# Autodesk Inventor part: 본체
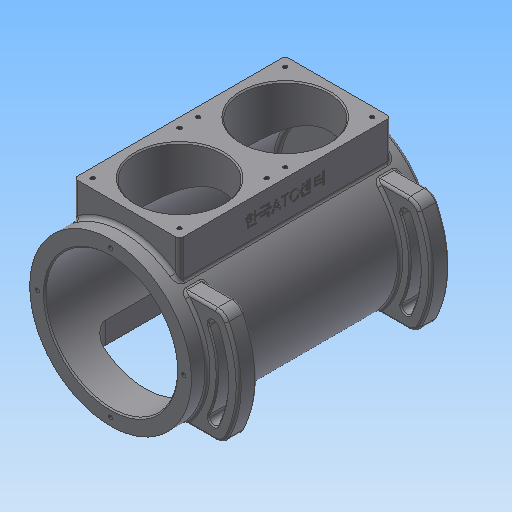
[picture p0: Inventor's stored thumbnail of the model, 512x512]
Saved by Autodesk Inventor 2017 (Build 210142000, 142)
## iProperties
Created: 2016-11
Part Number: 본체
Material: 알루미늄 6061
Document SubType Name: Modeling
Designer: mduedu
Density: 2.71 g/cm^3
Appearance: 기본값
Author: mduedu
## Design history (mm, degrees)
sketch "스케치1"
  geometry: C1 r 65 at (0, 0); 1 further point
  constraints: 1 centre point, 1 coincident
  dimensions: "d119" = 130 diameter of C1
extrude "돌출1" new body sketch "스케치1" distance "d3" = 98; taper "d4" = 0 deg; dims "d132" = 97, "d133" = 0
feature "쉘1" dims "d120" = 12, "d134" = 8
node "작업 평면2"
sketch "스케치13"
  geometry: L1 (42.5, 85)-(-42.5, 85); L2 (-42.5, 85)-(-42.5, -85); L3 (-42.5, -85)-(42.5, -85); L4 (42.5, -85)-(42.5, 85); 2 further points
  constraints: 8 end point, 2 parallel, 1 horizontal, 1 midpoint, 1 perpendicular, 1 vertical alignment
  dimensions: "d122" = 170 distance of L1.end L2.end; "d124" = 85 distance of L2.end L3.end; "d125" = 85 distance from line of point (0, 0) L1 (= 0.5 x d122)
extrude "돌출11" join sketch "스케치13" stored distance "d126" = 10; taper "d127" = 0 deg
sketch "스케치14"
  geometry: L1 (65, 97)-(-65, 97) reference; C1 r 35 at (0, 42.5); 1 further point
  constraints: 1 centre point, 1 vertical alignment
  dimensions: "d128" = 70 diameter of C1; "d129" = 54.5 distance from line of C1.centre L1
extrude "돌출12" cut sketch "스케치14" stored distance "d130" = 10; taper "d131" = 0 deg
sketch "스케치15"
  geometry: C1 r 53 at (0, 0) reference; 1 further point
extrude "돌출13" cut sketch "스케치15" stored distance "d135" = 10; taper "d136" = 0 deg
chamfer "모따기1" distance "d54" = 1; stored, may be unused: second distance "d55" = 2, angle "d56" = 45 deg
sketch "스케치8"
  geometry: C1 r 30 at (0, 0); C2 r 65 at (0, 0) reference; 1 further point
  constraints: 1 centre point, 1 concentric
  dimensions: "d57" = 60 diameter of C1
extrude "돌출8" join sketch "스케치8" distance "d58" = 14; taper "d59" = 0 deg
hole "구멍3" diameter "d62" = 41; stored, may be unused: countersink angle "d66" = 90 deg, drill point angle "d68" = 0 deg; dims "d63" = 6, "d64" = 47, "d65" = 14, "d67" = 17, "d195" = 10, "d196" = 10
fillet "모깎기11" dims "d69" = 3
fillet "모깎기12" dims "d70" = 3
fillet "모깎기13" dims "d71" = 0.3
chamfer "모따기2" distance "d72" = 1; stored, may be unused: second distance "d73" = 2, angle "d74" = 45 deg
node "작업 평면3"
sketch "스케치16"
  geometry: L1 (-42.5, -80)-(47.5, -80); L2 (-42.5, -80)-(21.14, -16.36); L3 (-42.5, -80)-(21.14, -143.64); L4 (3.462, -34.038)-(34.879, -34.038); L5 (3.462, -125.962)-(34.879, -125.962); A1 r 65 centre (-42.5, -80) between (3.462, -34.038) and (3.462, -125.962) reference; A2 r 90 centre (-42.5, -80) between (34.879, -125.962) and (34.879, -34.038); A3 r 90 centre (-42.5, -80) between (34.879, -34.038) and (34.879, -125.962); A4 r 65 centre (-42.5, -80) between (3.462, -125.962) and (3.462, -34.038); 1 further point
  constraints: 11 point on circle, 10 end point, 3 centre point, 2 parallel, 2 point on line, 1 coincident, 1 horizontal
  dimensions: "d140" = 45 deg angle of L3 L1; "d141" = 45 deg angle of L2 L1; "d142" = 25 radial gap between concentric circles of A1 A2
extrude "돌출14" join sketch "스케치16" distance "d143" = 15; taper "d144" = 0 deg
sketch "스케치17"
  geometry: L1 (-42.5, -80)-(34.414, -80); L2 (-42.5, -80)-(27.208, -47.495); L3 (-42.5, -80)-(27.208, -112.505); L4 (34.879, -34.038)-(3.462, -34.038) reference; L5 (3.462, -125.962)-(34.879, -125.962) reference; A1 r 65 centre (-42.5, -80) between (3.462, -34.038) and (3.462, -125.962) reference; A2 r 76.914 centre (-42.5, -80) between (19.17, -125.962) and (19.17, -34.038); A3 r 4 centre (27.208, -47.495) between (23.582, -49.185) and (30.833, -45.804); A4 r 4 centre (27.208, -112.505) between (30.833, -114.196) and (23.582, -110.815); A5 r 80.914 centre (-42.5, -80) between (30.833, -114.196) and (30.833, -45.804); A6 r 72.914 centre (-42.5, -80) between (23.582, -110.815) and (23.582, -49.185); 1 further point
  constraints: 13 point on circle, 6 end point, 5 centre point, 5 coincident, 3 midpoint, 2 point on line, 1 equal radius, 1 horizontal
  dimensions: "d145" = 25 deg angle of L1 L3; "d146" = 25 deg angle of L2 L1; "d147" = 8 diameter of A3
extrude "돌출15" cut sketch "스케치17" stored distance "d150" = 15; taper "d151" = 0 deg
fillet "모깎기17" dims "d152" = 10
fillet "모깎기18" dims "d153" = 2
fillet "모깎기19" dims "d154" = 2
chamfer "모따기4" distance "d155" = 1; stored, may be unused: second distance "d156" = 2, angle "d157" = 45 deg
fillet "모깎기20" dims "d159" = 3
fillet "모깎기21" dims "d160" = 3
fillet "모깎기22" dims "d161" = 3
node "작업 평면4"
sketch "스케치18"
  geometry: L1 (-42.5, 70)-(42.5, 70); L2 (42.5, 70)-(42.5, -70); L3 (42.5, -70)-(-42.5, -70); L4 (-42.5, -70)-(-42.5, 70); 2 further points
  constraints: 8 end point, 2 parallel, 1 horizontal, 1 midpoint, 1 perpendicular, 1 vertical alignment
  dimensions: "d162" = 140 distance of L1.end L2.end; "d164" = 85 distance of L2.end L3.end; "d165" = 70 distance from line of point (0, 0) L1 (= 0.5 x d162)
extrude "돌출16" cut sketch "스케치18" stored distance "d166" = 15; taper "d167" = 0 deg
fillet "모깎기23" dims "d168" = 10
fillet "모깎기24" dims "d173" = 3
sketch "스케치19"
  geometry: 4 further points
  constraints: 4 other
hole "구멍6" sketch "스케치19" at (0, -59), (59, 0), (-59, 0), (0, 59) diameter "d174" = 3.242; stored, may be unused: countersink angle "d178" = 90 deg, drill point angle "d180" = 120 deg; dims "d175" = 8, "d176" = 4, "d177" = 2, "d179" = 10
sketch "스케치20"
  geometry: L1 (35, -77.5)-(-35, -77.5); L2 (-35, -77.5)-(-35, -7.5); L3 (-35, -7.5)-(35, -7.5); L4 (35, -7.5)-(35, -77.5); L5 (35, -77.5)-(-35, -7.5); L6 (-35, -77.5)-(35, -7.5); C1 r 36 at (0, -42.5) reference; 5 further points
  constraints: 12 end point, 4 coincident, 2 midpoint, 2 parallel, 1 horizontal, 1 perpendicular
  dimensions: "d181" = 70 distance of L2.end L3.end; "d182" = 70 distance of L1.end L2.end
hole "구멍7" sketch "스케치20" at (-35, -77.5), (-35, -7.5), (35, -7.5), (35, -77.5) diameter "d183" = 3.242; stored, may be unused: countersink angle "d187" = 90 deg, drill point angle "d189" = 118 deg; dims "d184" = 8, "d185" = 4, "d186" = 2, "d188" = 10
sketch "스케치21"
  geometry: L1 (164, 0)-(0, 0) reference; L2 (-3, 0)-(-3, -24.649) reference; 3 further points
  constraints: 1 midpoint, 1 vertical alignment, 1 other
  dimensions: "d190" = 15 distance from line of point (82, -15) L1; "d191" = 85 distance from line of point (82, 0) L2 (derived)
feature "엠보싱2" sketch "스케치21" dims "d3" = 98, "d4" = 0, "d119" = 130, "d132" = 97, "d133" = 0, "d192" = 0.5, "d193" = 0
node "솔리드1"
mirror "대칭5"
mirror "대칭6"
mirror "대칭7"
